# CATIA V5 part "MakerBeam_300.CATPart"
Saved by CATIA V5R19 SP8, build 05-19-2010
Part number: Profilé Makebeam 300
Definition: Profilé Makebeam 300
Nomenclature: MakerBeam_100102
Bounding box of the stored display mesh (mm): x 0 to 300, y -5 to 5, z -5 to 5
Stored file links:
  D:\Documents\1_Travail\1 - ac-limoges.fr\ac-limoges.fr\Emmanuel Maynard - STI2D_Turgot\1 - IT-I2D\Activités_IT_Première\IT_3_Abris_bus\Maquettes numériques\Abribus_eleve\MakerBeam_300.CATPart
  C:\Program Files\Dassault Systemes\B19\win_b64\reffiles\standard\MetricThickPitch.txt
  D:\Documents\1_Travail\2- 2I2D\6 -  Ressources ITEC\Ressources Techniques\0-Maquettes numériques_Composants\Catalogue_Makeblock\Catalog_Makeblock\12_MakerBeam\TableMakerbeam.xls
  D:\Documents\1_Travail\2- 2I2D\6 -  Ressources ITEC\Ressources Techniques\0-Maquettes numériques_Composants\Catalogue_Makeblock\Catalog_Makeblock\12_MakerBeam\TableMakerbeam.txt
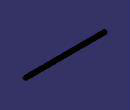
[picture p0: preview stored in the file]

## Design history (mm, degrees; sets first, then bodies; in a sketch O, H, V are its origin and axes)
Parameters
  Longueur = 300 mm
  `Désignation` = "Profilé Makebeam 300"
  `Référence` = "MakerBeam_100102"
AxisSystem1: origin (0, 0, 0), X (1, 0, 0), Y (0, 1, 0), Z (0, 0, 1)
Body1 (main body)
  Sketch1 on YZ plane of AxisSystem1, origin (0, 0, 0), H (0, 1, 0), V (0, 0, 1)
    line L1 (-5, 5) -> (-1.5, 5)
    point P1 (5, 5)
    point P2 (-5, 5)
    arc A1 centre (0, 0) radius 1.2 from (0, 1.2) to (-0.8485, 0.8485) ccw
    line L2 (-0.8485, 0.8485) -> (-5, 5)
    line L3 (0, 1.2) -> (0, 2)
    reference intersected line E1 through (0, 0) direction (-1, 0) from XY plane of AxisSystem1
    reference intersected line E2 through (0, 0) direction (0, 1) from ZX plane of AxisSystem1
    line L4 (-1.5, 5) -> (-1.5, 4)
    line L5 (-1.5, 4) -> (-3.2929, 4)
    line L6 (-3.2929, 4) -> (-1, 2)
    line L7 (-1, 2) -> (0, 2)
    reference projected line E3 through (0, 0) direction (0, 1) from edge [ZX plane of AxisSystem1 | YZ plane of AxisSystem1]
    radius A1 = 1.2
    distance L1 E1 = 5
    distance P2 E3 = 5
    distance L4 P2 = 3.5
    length L7 = 1
    distance L5 L1 = 1
    distance L7 L1 = 3
    angle L6 L3 = 48.903
    horizontal: L1 H, L5 H, L7 H
    vertical: L3 V, L4 V
    coincidence: L3 E2, L2 O
  Pad1: profile Sketch1, direction (1, 0, 0), length 300 {= Longueur}
  Fillet1: radius 0.2, on edge [face of Pad1 from Sketch1.L5 | face of Pad1 from Sketch1.L6]; edge [face of Pad1 from Sketch1.L6 | face of Pad1 from Sketch1.L7]; edge [face of Pad1 from Sketch1.L1 | face of Pad1 from Sketch1.L4]; edge [face of Pad1 from Sketch1.L4 | face of Pad1 from Sketch1.L5]
  Mirror1: of the body so far, about face of Pad1 from Sketch1.L2
  Fillet2: radius 0.2, on edge [face of Mirror1 | face of Pad1 from Sketch1.L1]
  Mirror2: of the body so far, about face of Mirror1
  Mirror3: of the body so far, about face of Pad1 from Sketch1.L3
  Sketch2 on face of Pad1, origin (300, 0.9666, 1.0824), H (0, 1, 0), V (0, 0, 1)
    point P1 (-0.9666, -1.0824)
    projected point E1 (-0.9666, -1.0824) from axis of face of Mirror3
    coincidence: E1 P1
  Hole1: placed by Sketch2, at (300, 0, 0) direction (-1, 0, 0), diameter 2.459, depth 10, threaded "M3", thread diameter 3, thread depth 8, pitch 0.5
  Sketch3 on face of Pad1, origin (0, -1.3866, 1.2369), H (0, 1, 0), V (0, 0, -1)
    point P1 (1.3866, 1.2369)
    reference projected point E1 (1.3866, 1.2369) from axis of face of Pad1
    coincidence: P1 E1
  Hole2: placed by Sketch3, at (0, 0, 0) direction (1, 0, 0), diameter 2.459, depth 10, threaded "M3", thread diameter 3, thread depth 8, pitch 0.5
Current feature: Mirror3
